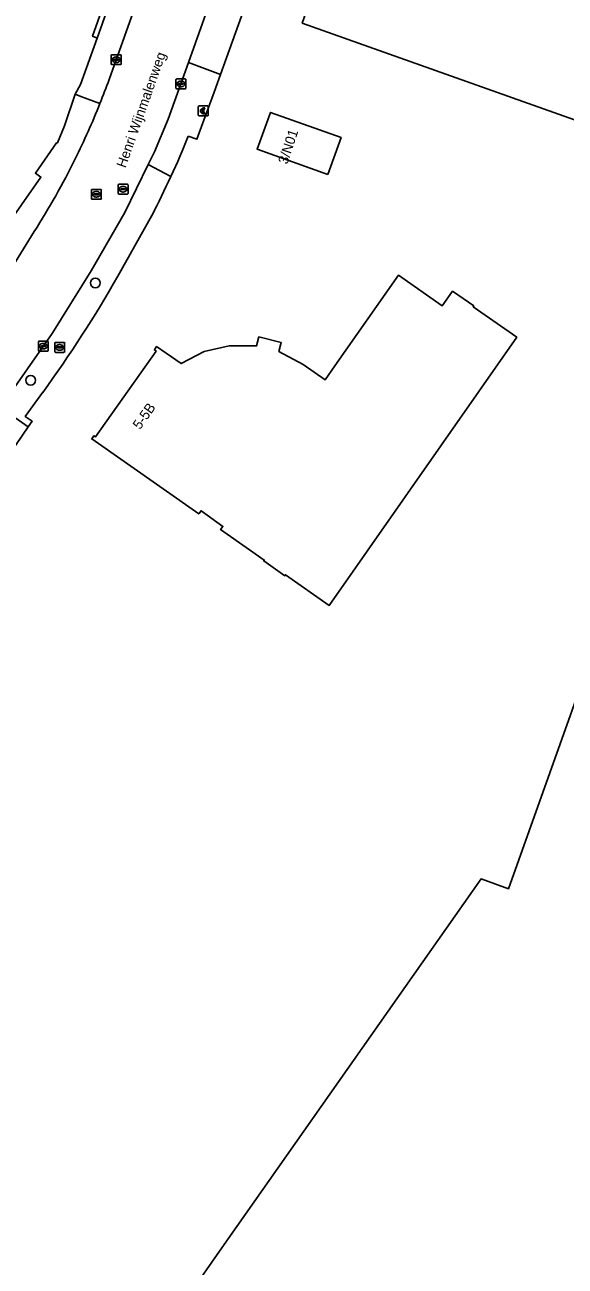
# Model space of a CAD drawing. Extents: x 155018 to 156648, y 383979 to 385733.
# Drawn here: x 155506.9 to 155561.5, y 385022.6 to 385148 of the extents above; entities that cross this region are included whole.
import ezdxf

# ---------------------------------------------------------------- set-up
doc = ezdxf.new("R2010")
doc.units = 0
for name, color, linetype in [('IMGEO_Betaalautomaat', 7, 'Continuous'), ('IMGEO_Boom', 7, 'Continuous'), ('IMGEO_Brandkraan', 7, 'Continuous'), ('IMGEO_Erf', 7, 'Continuous'), ('IMGEO_Kolk', 7, 'Continuous'), ('IMGEO_Openbare_ruimte_label', 7, 'Continuous'), ('IMGEO_Pand', 7, 'Continuous'), ('IMGEO_Pand_nummerreeks', 7, 'Continuous'), ('IMGEO_Parkeervlak_open', 7, 'Continuous'), ('IMGEO_Rijbaan_lokaal_gesloten', 7, 'Continuous'), ('IMGEO_Rijbaan_lokaal_open', 7, 'Continuous'), ('IMGEO_Rioolput', 7, 'Continuous'), ('IMGEO_Voetpad_open', 7, 'Continuous')]:
    doc.layers.add(name, color=color, linetype=linetype)

msp = doc.modelspace()

# ---------------------------------------------------------------- linework, layer by layer
at = {"layer": 'IMGEO_Betaalautomaat'}
for p, q in [((155524.45, 385138.91), (155524.45, 385139.75)), ((155524.45, 385139.75), (155524.45, 385138.91)), ((155524.52, 385139.83), (155525.36, 385139.83)), ((155525.36, 385139.83), (155524.52, 385139.83)), ((155525.11, 385139.64), (155525.09, 385139.54)), ((155525.45, 385139.76), (155525.45, 385138.92)), ((155525.45, 385138.92), (155525.45, 385139.76)), ((155525.37, 385138.83), (155524.53, 385138.83)), ((155524.53, 385138.83), (155525.37, 385138.83)), ((155524.73, 385139.29), (155524.73, 385139.36)), ((155524.85, 385139.36), (155524.85, 385139.29)), ((155525.1, 385139.13), (155525.12, 385139.04))]:
    msp.add_line(p, q, dxfattribs=at)
for points in [[(155524.73, 385139.36), (155524.66, 385139.36), (155524.66, 385139.43), (155524.74, 385139.43)], [(155524.74, 385139.23), (155524.66, 385139.23), (155524.66, 385139.29), (155524.73, 385139.29)], [(155524.86, 385139.43), (155525.01, 385139.43), (155525.01, 385139.36), (155524.85, 385139.36)], [(155524.85, 385139.29), (155525.01, 385139.29), (155525.01, 385139.23), (155524.87, 385139.23)]]:
    msp.add_lwpolyline(points, dxfattribs=at)
for centre, radius, start, end in [((155524.53, 385139.75), 0.0779, 92.4484, 184.2845), ((155524.53, 385139.75), 0.0779, 92.4484, 184.2845), ((155525.03, 385139.36), 0.293, 73.014, 165.0139), ((155525.37, 385139.75), 0.0779, 2.4484, 94.2845), ((155525.37, 385139.75), 0.0779, 2.4484, 94.2845), ((155524.53, 385138.91), 0.0779, 182.4484, 274.2845), ((155524.53, 385138.91), 0.0779, 182.4484, 274.2845), ((155525, 385139.28), 0.267, 191.8096, 297.0389), ((155525.03, 385139.37), 0.179, 69.3236, 159.5683), ((155525.03, 385139.3), 0.179, 202.7625, 291.8693), ((155525.37, 385138.91), 0.0779, 272.4484, 4.2845), ((155525.37, 385138.91), 0.0779, 272.4484, 4.2845)]:
    msp.add_arc(centre, radius, start, end, dxfattribs=at)
at = {"layer": 'IMGEO_Boom'}
for centre in [(155514.04, 385121.94), (155507.51, 385112.11)]:
    msp.add_circle(centre, 0.489, dxfattribs=at)
at = {"layer": 'IMGEO_Brandkraan'}
for p, q in [((155509.95, 385115.01), (155509.95, 385115.86)), ((155510.03, 385115.93), (155510.88, 385115.93)), ((155510.95, 385115.86), (155510.95, 385115.01)), ((155510.88, 385114.93), (155510.03, 385114.93)), ((155510.21, 385115.43), (155510.21, 385115.44)), ((155510.25, 385115.48), (155510.65, 385115.48)), ((155510.65, 385115.39), (155510.25, 385115.39)), ((155510.44, 385115.71), (155510.46, 385115.71)), ((155510.46, 385115.15), (155510.44, 385115.15)), ((155510.69, 385115.44), (155510.69, 385115.43))]:
    msp.add_line(p, q, dxfattribs=at)
for points in [[(155509.95, 385115.01), (155509.95, 385115.86)], [(155510.03, 385115.93), (155510.88, 385115.93)], [(155510.95, 385115.86), (155510.95, 385115.01)], [(155510.88, 385114.93), (155510.03, 385114.93)]]:
    msp.add_lwpolyline(points, dxfattribs=at)
for centre, radius, start, end in [((155510.03, 385115.86), 0.0765, 91.552, 178.448), ((155510.03, 385115.86), 0.0765, 91.552, 178.448), ((155510.88, 385115.86), 0.0765, 1.552, 88.448), ((155510.88, 385115.86), 0.0765, 1.552, 88.448), ((155510.03, 385115.01), 0.0765, 181.552, 268.448), ((155510.03, 385115.01), 0.0765, 181.552, 268.448), ((155510.25, 385115.44), 0.0403, 85.8775, 175.7526), ((155510.25, 385115.43), 0.0366, 178.938, 274.7102), ((155510.66, 385115.44), 0.0386, 1.7309, 96.639), ((155510.65, 385115.43), 0.043, 264.8664, 352.4533), ((155510.88, 385115.01), 0.0765, 271.552, 358.448), ((155510.88, 385115.01), 0.0765, 271.552, 358.448)]:
    msp.add_arc(centre, radius, start, end, dxfattribs=at)
for centre, major_axis, ratio, start_param, end_param in [((155510.44, 385115.43), (-0.387, 0.002), 0.722429, 4.712389, 7.853982), ((155510.46, 385115.43), (-0.39, 0.002), 0.717154, 1.570796, 4.712389)]:
    msp.add_ellipse(centre, major_axis=major_axis, ratio=ratio, start_param=start_param, end_param=end_param, dxfattribs=at)
at = {"layer": 'IMGEO_Erf'}
for points in [[(155694.34, 384956.98), (155694.92, 384958.59), (155709.08, 384998.08), (155709.77, 385000), (155717.52, 385021.63), (155721.8, 385033.58), (155723.78, 385039.19), (155749.44, 385111.62), (155754.28, 385125.28), (155751.4, 385130.42), (155717.6, 385142.4), (155670.01, 385159.25), (155661.24, 385162.35), (155620.24, 385176.93), (155602.3, 385183.3), (155601.27, 385183.67), (155551.45, 385201.4), (155546.6, 385198.73), (155542.42, 385187.25), (155529.71, 385151.46), (155526.7, 385143.01), (155526.06, 385141.21), (155524.3, 385136.46), (155523.43, 385136.78)], [(155481.2, 385089.66), (155480.12, 385092.29), (155488, 385103.31), (155488.18, 385103.57), (155489.14, 385104.92), (155492.96, 385110.32), (155495.74, 385114.25), (155500, 385120.25), (155500.79, 385121.37), (155500.69, 385121.46), (155508.55, 385132.63), (155507.99, 385133.03), (155510.14, 385136.11), (155510.23, 385136.1), (155510.94, 385137.8), (155512.01, 385141.01), (155512.55, 385141.98), (155514.24, 385146.67), (155513.77, 385146.87), (155529.19, 385190.29)], [(155519.74, 385128.74), (155516.32, 385122.63)], [(155508.73, 385110.89), (155506.97, 385108.46), (155507.67, 385107.97), (155507.27, 385107.39), (155505.4, 385104.69), (155500.79, 385097.95), (155500, 385096.82), (155478.38, 385065.97), (155465.22, 385047.19), (155455.9, 385033.94)], [(155535.47, 385004.27), (155535.99, 385004.27), (155536.34, 385005.32), (155535.9, 385005.46), (155529.1, 385007.89), (155532.32, 385016.92), (155523.71, 385020.02), (155526.58, 385024.11), (155553.01, 385061.73), (155555.77, 385060.74), (155568.46, 385096.34), (155630.02, 385074.4), (155603.52, 385000)]]:
    msp.add_lwpolyline(points, dxfattribs=at)
for points in [[(155564.35, 385122.44), (155569.18, 385136.03), (155534.94, 385148.2), (155545.92, 385179.11), (155547.38, 385178.75), (155551.81, 385178.73), (155553.29, 385178.36), (155554, 385180.39), (155574.93, 385172.93), (155575.01, 385172.91), (155581.82, 385170.48), (155577.59, 385158.61), (155588.82, 385154.6), (155575.94, 385118.32)], [(155537.52, 385132.91), (155530.39, 385135.47), (155531.74, 385139.17), (155538.86, 385136.63)], [(155537.67, 385089.36), (155533.25, 385092.45), (155533.19, 385092.36), (155531.05, 385093.85), (155531.11, 385093.94), (155529.62, 385094.99), (155526.7, 385097.02), (155526.93, 385097.35), (155524.73, 385098.93), (155524.5, 385098.6), (155513.68, 385106.18), (155513.91, 385106.51), (155514.08, 385106.4), (155520.18, 385115.06), (155520.01, 385115.18), (155520.24, 385115.51), (155521.21, 385114.84), (155522.7, 385113.79), (155525.05, 385115), (155527.58, 385115.59), (155530.34, 385115.58), (155530.57, 385116.49), (155532.82, 385115.92), (155532.59, 385115.02), (155535.03, 385113.71), (155537.25, 385112.15), (155538.23, 385113.56), (155544.65, 385122.72), (155549.06, 385119.62), (155550.12, 385121.11), (155552.26, 385119.62), (155552.2, 385119.53), (155556.6, 385116.46)]]:
    msp.add_lwpolyline(points, close=True, dxfattribs=at)
for centre, radius, start, end in [((155435.94, 385172.05), 94.34, 335.3543, 338.0447), ((155437.43, 385171.44), 92.73, 332.5779, 335.3115), ((155409.79, 385183.12), 122.51, 323.87, 330.4118)]:
    msp.add_arc(centre, radius, start, end, dxfattribs=at)
at = {"layer": 'IMGEO_Kolk'}
for p, q in [((155515.66, 385144.07), (155515.66, 385144.93)), ((155515.73, 385145), (155516.58, 385145)), ((155516.15, 385144.78), (155516.17, 385144.78)), ((155516.66, 385144.93), (155516.66, 385144.07)), ((155516.58, 385144), (155515.73, 385144)), ((155515.92, 385144.49), (155515.92, 385144.51)), ((155515.96, 385144.54), (155516.36, 385144.54)), ((155516.35, 385144.46), (155515.96, 385144.46)), ((155516.17, 385144.22), (155516.14, 385144.22)), ((155516.4, 385144.51), (155516.4, 385144.49)), ((155522.19, 385141.62), (155522.19, 385142.48)), ((155522.27, 385142.55), (155523.12, 385142.55)), ((155522.68, 385142.33), (155522.71, 385142.33)), ((155523.2, 385142.48), (155523.2, 385141.62)), ((155523.12, 385141.55), (155522.27, 385141.55)), ((155522.45, 385142.04), (155522.45, 385142.06)), ((155522.89, 385142.01), (155522.49, 385142.01)), ((155522.5, 385142.09), (155522.89, 385142.09)), ((155522.7, 385141.77), (155522.68, 385141.77)), ((155522.94, 385142.06), (155522.94, 385142.04)), ((155508.3, 385115.12), (155508.3, 385115.98)), ((155508.37, 385116.05), (155509.22, 385116.05)), ((155508.78, 385115.83), (155508.81, 385115.83)), ((155509.3, 385115.98), (155509.3, 385115.12)), ((155509.22, 385115.05), (155508.37, 385115.05)), ((155508.55, 385115.54), (155508.55, 385115.56)), ((155508.99, 385115.51), (155508.59, 385115.51)), ((155508.6, 385115.59), (155508.99, 385115.59)), ((155508.81, 385115.27), (155508.78, 385115.27)), ((155509.04, 385115.56), (155509.04, 385115.54))]:
    msp.add_line(p, q, dxfattribs=at)
for points in [[(155515.66, 385144.07), (155515.66, 385144.93)], [(155515.73, 385145), (155516.58, 385145)], [(155516.66, 385144.93), (155516.66, 385144.07)], [(155516.58, 385144), (155515.73, 385144)], [(155522.19, 385141.62), (155522.19, 385142.48)], [(155522.27, 385142.55), (155523.12, 385142.55)], [(155523.2, 385142.48), (155523.2, 385141.62)], [(155523.12, 385141.55), (155522.27, 385141.55)], [(155508.3, 385115.12), (155508.3, 385115.98)], [(155508.37, 385116.05), (155509.22, 385116.05)], [(155509.3, 385115.98), (155509.3, 385115.12)], [(155509.22, 385115.05), (155508.37, 385115.05)]]:
    msp.add_lwpolyline(points, dxfattribs=at)
for centre, radius, start, end in [((155515.73, 385144.92), 0.0765, 91.552, 178.448), ((155515.73, 385144.92), 0.0765, 91.552, 178.448), ((155516.58, 385144.92), 0.0765, 1.552, 88.448), ((155516.58, 385144.92), 0.0765, 1.552, 88.448), ((155515.73, 385144.07), 0.0765, 181.552, 268.448), ((155515.73, 385144.07), 0.0765, 181.552, 268.448), ((155515.96, 385144.5), 0.0403, 85.8775, 175.7526), ((155515.95, 385144.49), 0.0366, 178.938, 274.7102), ((155516.36, 385144.5), 0.043, 264.8664, 352.4533), ((155516.36, 385144.5), 0.0386, 1.7309, 96.639), ((155516.58, 385144.07), 0.0765, 271.552, 358.448), ((155516.58, 385144.07), 0.0765, 271.552, 358.448), ((155522.27, 385142.47), 0.0765, 91.552, 178.448), ((155522.27, 385142.47), 0.0765, 91.552, 178.448), ((155523.12, 385142.47), 0.0765, 1.552, 88.448), ((155523.12, 385142.47), 0.0765, 1.552, 88.448), ((155522.27, 385141.63), 0.0765, 181.552, 268.448), ((155522.27, 385141.63), 0.0765, 181.552, 268.448), ((155522.49, 385142.05), 0.0403, 85.8775, 175.7526), ((155522.49, 385142.04), 0.0366, 178.938, 274.7102), ((155522.9, 385142.05), 0.0386, 1.7309, 96.639), ((155522.89, 385142.05), 0.043, 264.8664, 352.4533), ((155523.12, 385141.63), 0.0765, 271.552, 358.448), ((155523.12, 385141.63), 0.0765, 271.552, 358.448), ((155508.37, 385115.97), 0.0765, 91.552, 178.448), ((155508.37, 385115.97), 0.0765, 91.552, 178.448), ((155509.22, 385115.97), 0.0765, 1.552, 88.448), ((155509.22, 385115.97), 0.0765, 1.552, 88.448), ((155508.37, 385115.13), 0.0765, 181.552, 268.448), ((155508.37, 385115.13), 0.0765, 181.552, 268.448), ((155508.59, 385115.55), 0.0403, 85.8775, 175.7526), ((155508.59, 385115.54), 0.0366, 178.938, 274.7102), ((155509, 385115.55), 0.0386, 1.7309, 96.639), ((155509, 385115.55), 0.043, 264.8664, 352.4533), ((155509.22, 385115.13), 0.0765, 271.552, 358.448), ((155509.22, 385115.13), 0.0765, 271.552, 358.448)]:
    msp.add_arc(centre, radius, start, end, dxfattribs=at)
for centre, major_axis, ratio, start_param, end_param in [((155516.14, 385144.5), (-0.387, 0.002), 0.722429, 4.712389, 7.853982), ((155516.17, 385144.5), (-0.39, 0.002), 0.717154, 1.570796, 4.712389), ((155522.68, 385142.05), (-0.387, 0.002), 0.722429, 4.712389, 7.853982), ((155522.71, 385142.05), (-0.39, 0.002), 0.717154, 1.570796, 4.712389), ((155508.78, 385115.55), (-0.387, 0.002), 0.722429, 4.712389, 7.853982), ((155508.81, 385115.55), (-0.39, 0.002), 0.717154, 1.570796, 4.712389)]:
    msp.add_ellipse(centre, major_axis=major_axis, ratio=ratio, start_param=start_param, end_param=end_param, dxfattribs=at)
at = {"layer": 'IMGEO_Pand'}
for points in [[(155588.82, 385154.6), (155577.59, 385158.61), (155581.82, 385170.48), (155575.01, 385172.91), (155574.93, 385172.93), (155554, 385180.39), (155553.29, 385178.36), (155551.81, 385178.73), (155547.38, 385178.75), (155545.92, 385179.11), (155534.94, 385148.2), (155569.18, 385136.03), (155564.35, 385122.44), (155575.94, 385118.32)], [(155537.52, 385132.91), (155538.86, 385136.63), (155531.74, 385139.17), (155530.39, 385135.47)], [(155521.21, 385114.84), (155520.24, 385115.51), (155520.01, 385115.18), (155520.18, 385115.06), (155514.08, 385106.4), (155513.91, 385106.51), (155513.68, 385106.18), (155524.5, 385098.6), (155524.73, 385098.93), (155526.93, 385097.35), (155526.7, 385097.02), (155529.62, 385094.99), (155531.11, 385093.94), (155531.05, 385093.85), (155533.19, 385092.36), (155533.25, 385092.45), (155537.67, 385089.36), (155556.6, 385116.46), (155552.2, 385119.53), (155552.26, 385119.62), (155550.12, 385121.11), (155549.06, 385119.62), (155544.65, 385122.72), (155538.23, 385113.56), (155537.25, 385112.15), (155535.03, 385113.71), (155532.59, 385115.02), (155532.82, 385115.92), (155530.57, 385116.49), (155530.34, 385115.58), (155527.58, 385115.59), (155525.05, 385115), (155522.7, 385113.79)]]:
    msp.add_lwpolyline(points, close=True, dxfattribs=at)
msp.add_lwpolyline([(155568.46, 385096.34), (155555.77, 385060.74), (155553.01, 385061.73), (155526.58, 385024.11), (155523.71, 385020.02), (155532.32, 385016.92), (155529.1, 385007.89), (155535.9, 385005.46), (155536.34, 385005.32), (155535.99, 385004.27), (155535.47, 385004.27)], dxfattribs=at)
at = {"layer": 'IMGEO_Parkeervlak_open'}
for points in [[(155528.83, 385187.83), (155514.24, 385146.67), (155512.55, 385141.98), (155512.01, 385141.01), (155512.57, 385140.78), (155514.51, 385140.06)], [(155515.45, 385142.5), (155531.64, 385187.95)]]:
    msp.add_lwpolyline(points, dxfattribs=at)
msp.add_arc((155440.16, 385169.94), 80.13, 338.1083, 339.9714, dxfattribs=at)
at = {"layer": 'IMGEO_Rijbaan_lokaal_gesloten'}
for points in [[(155497.6, 385099.6), (155497.89, 385100), (155500, 385103), (155504.46, 385109.35), (155509.68, 385116.82), (155513.64, 385123.17), (155517.04, 385129.07), (155519.39, 385133.9), (155520.02, 385135.19), (155521.4, 385138.49), (155522.69, 385142.05), (155523.46, 385144.21), (155526.46, 385152.66), (155530.45, 385163.87), (155534.19, 385174.38), (155539.73, 385189.98), (155540.75, 385192.84), (155534.18, 385195.18), (155532.1, 385189.25), (155531.64, 385187.95), (155515.45, 385142.5)], [(155507.88, 385127.15), (155504.08, 385121.01), (155503.18, 385119.65), (155500, 385115.17), (155498.16, 385112.57), (155495.38, 385108.61), (155491.55, 385103.16), (155491.43, 385103.02), (155481.12, 385088.28), (155456.45, 385053.11), (155451.96, 385046.71), (155447.5, 385040.32)]]:
    msp.add_lwpolyline(points, dxfattribs=at)
for centre, radius, start, end in [((155440.16, 385169.94), 80.13, 338.1083, 339.9714), ((155442.07, 385169.16), 78.07, 333.6256, 338.1187), ((155441.61, 385169.35), 78.57, 327.5077, 333.6493)]:
    msp.add_arc(centre, radius, start, end, dxfattribs=at)
at = {"layer": 'IMGEO_Rijbaan_lokaal_open'}
for points in [[(155529.71, 385151.46), (155527.45, 385152.29), (155535.15, 385174.02), (155534.19, 385174.38), (155530.45, 385163.87), (155526.46, 385152.66), (155523.46, 385144.21), (155526.7, 385143.01)], [(155505.4, 385104.69), (155507.27, 385107.39), (155504.46, 385109.35), (155500, 385103), (155497.89, 385100), (155500, 385098.51), (155500.79, 385097.95)]]:
    msp.add_lwpolyline(points, close=True, dxfattribs=at)
at = {"layer": 'IMGEO_Rioolput'}
for p, q in [((155513.65, 385130.47), (155513.65, 385131.32)), ((155513.73, 385131.4), (155514.58, 385131.4)), ((155513.91, 385130.89), (155513.91, 385130.9)), ((155513.95, 385130.94), (155514.35, 385130.94)), ((155514.35, 385130.85), (155513.95, 385130.85)), ((155514.14, 385131.18), (155514.16, 385131.18)), ((155514.39, 385130.9), (155514.39, 385130.89)), ((155514.65, 385131.32), (155514.65, 385130.47)), ((155516.35, 385130.99), (155516.35, 385131.84)), ((155516.42, 385131.91), (155517.28, 385131.91)), ((155517.28, 385130.91), (155516.42, 385130.91)), ((155516.61, 385131.41), (155516.61, 385131.42)), ((155516.65, 385131.46), (155517.05, 385131.46)), ((155517.05, 385131.37), (155516.65, 385131.37)), ((155516.86, 385131.13), (155516.83, 385131.13)), ((155516.84, 385131.69), (155516.86, 385131.69)), ((155517.09, 385131.42), (155517.09, 385131.41)), ((155517.35, 385131.84), (155517.35, 385130.99)), ((155514.58, 385130.4), (155513.73, 385130.4)), ((155514.16, 385130.62), (155514.14, 385130.62))]:
    msp.add_line(p, q, dxfattribs=at)
for points in [[(155513.65, 385130.47), (155513.65, 385131.32)], [(155513.73, 385131.4), (155514.58, 385131.4)], [(155514.65, 385131.32), (155514.65, 385130.47)], [(155516.35, 385130.99), (155516.35, 385131.84)], [(155516.42, 385131.91), (155517.28, 385131.91)], [(155517.28, 385130.91), (155516.42, 385130.91)], [(155517.35, 385131.84), (155517.35, 385130.99)], [(155514.58, 385130.4), (155513.73, 385130.4)]]:
    msp.add_lwpolyline(points, dxfattribs=at)
for centre, radius, start, end in [((155513.73, 385131.32), 0.0765, 91.552, 178.448), ((155513.73, 385131.32), 0.0765, 91.552, 178.448), ((155513.95, 385130.9), 0.0403, 85.8775, 175.7526), ((155513.95, 385130.89), 0.0366, 178.938, 274.7102), ((155514.36, 385130.9), 0.0386, 1.7309, 96.639), ((155514.35, 385130.9), 0.043, 264.8664, 352.4533), ((155514.58, 385131.32), 0.0765, 1.552, 88.448), ((155514.58, 385131.32), 0.0765, 1.552, 88.448), ((155516.43, 385131.84), 0.0765, 91.552, 178.448), ((155516.43, 385131.84), 0.0765, 91.552, 178.448), ((155516.43, 385130.99), 0.0765, 181.552, 268.448), ((155516.43, 385130.99), 0.0765, 181.552, 268.448), ((155516.65, 385131.42), 0.0403, 85.8775, 175.7526), ((155516.64, 385131.41), 0.0366, 178.938, 274.7102), ((155517.05, 385131.42), 0.0386, 1.7309, 96.639), ((155517.05, 385131.41), 0.043, 264.8664, 352.4533), ((155517.27, 385131.84), 0.0765, 1.552, 88.448), ((155517.27, 385131.84), 0.0765, 1.552, 88.448), ((155517.27, 385130.99), 0.0765, 271.552, 358.448), ((155517.27, 385130.99), 0.0765, 271.552, 358.448), ((155513.73, 385130.47), 0.0765, 181.552, 268.448), ((155513.73, 385130.47), 0.0765, 181.552, 268.448), ((155514.58, 385130.47), 0.0765, 271.552, 358.448), ((155514.58, 385130.47), 0.0765, 271.552, 358.448)]:
    msp.add_arc(centre, radius, start, end, dxfattribs=at)
for centre, major_axis, ratio, start_param, end_param in [((155514.14, 385130.9), (-0.387, 0.002), 0.722429, 4.712389, 7.853982), ((155514.16, 385130.9), (-0.39, 0.002), 0.717154, 1.570796, 4.712389), ((155516.84, 385131.41), (-0.387, 0.002), 0.722429, 4.712389, 7.853982), ((155516.86, 385131.41), (-0.39, 0.002), 0.717154, 1.570796, 4.712389)]:
    msp.add_ellipse(centre, major_axis=major_axis, ratio=ratio, start_param=start_param, end_param=end_param, dxfattribs=at)
at = {"layer": 'IMGEO_Voetpad_open'}
for points in [[(155531.64, 385187.95), (155532.1, 385189.25), (155529.19, 385190.29), (155513.77, 385146.87), (155514.24, 385146.67), (155528.83, 385187.83)], [(155523.43, 385136.78), (155524.3, 385136.46), (155526.06, 385141.21), (155526.7, 385143.01), (155523.46, 385144.21), (155522.69, 385142.05), (155521.4, 385138.49), (155520.02, 385135.19), (155519.39, 385133.9), (155521.68, 385132.71)], [(155514.51, 385140.06), (155512.57, 385140.78), (155512.01, 385141.01), (155510.94, 385137.8), (155510.23, 385136.1), (155510.14, 385136.11), (155507.99, 385133.03), (155508.55, 385132.63), (155500.69, 385121.46), (155500.79, 385121.37), (155500, 385120.25), (155495.74, 385114.25), (155498.16, 385112.57), (155500, 385115.17), (155503.18, 385119.65), (155504.08, 385121.01), (155507.88, 385127.15)], [(155521.68, 385132.71), (155519.39, 385133.9), (155517.04, 385129.07), (155513.64, 385123.17), (155509.68, 385116.82), (155504.46, 385109.35), (155507.27, 385107.39), (155507.67, 385107.97), (155506.97, 385108.46), (155508.73, 385110.89)], [(155516.32, 385122.63), (155519.74, 385128.74)]]:
    msp.add_lwpolyline(points, dxfattribs=at)
for centre, radius, start, end in [((155442.07, 385169.16), 78.07, 333.6256, 338.1187), ((155435.94, 385172.05), 94.34, 335.3543, 338.0447), ((155441.61, 385169.35), 78.57, 327.5077, 333.6493), ((155437.43, 385171.44), 92.73, 332.5779, 335.3115), ((155409.79, 385183.12), 122.51, 323.87, 330.4118)]:
    msp.add_arc(centre, radius, start, end, dxfattribs=at)

# ---------------------------------------------------------------- texts
at = {"layer": 'IMGEO_Openbare_ruimte_label'}
msp.add_text('Henri Wijnmalenweg', height=1, rotation=70.4964, dxfattribs=at).set_placement((155517.09, 385133.5))
at = {"layer": 'IMGEO_Pand_nummerreeks'}
for s, rotation, p in [('3/N01', 71.6915, (155533.43, 385133.87)), ('5-5B', 54.8733, (155518.56, 385107.06))]:
    msp.add_text(s, height=1, rotation=rotation, dxfattribs=at).set_placement(p)

doc.saveas('drawing.dxf')
